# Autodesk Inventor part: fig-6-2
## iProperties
Created: 2004-05
Part Number: fig-6-2
Document SubType Name: Modeling
Designer: CADCIM Technologies
Manufacturer: Standard
Standards Organization: Custom
Author: CADCIM Technologies
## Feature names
1. Extrusion1
2. Hole1
3. Circular Pattern1
